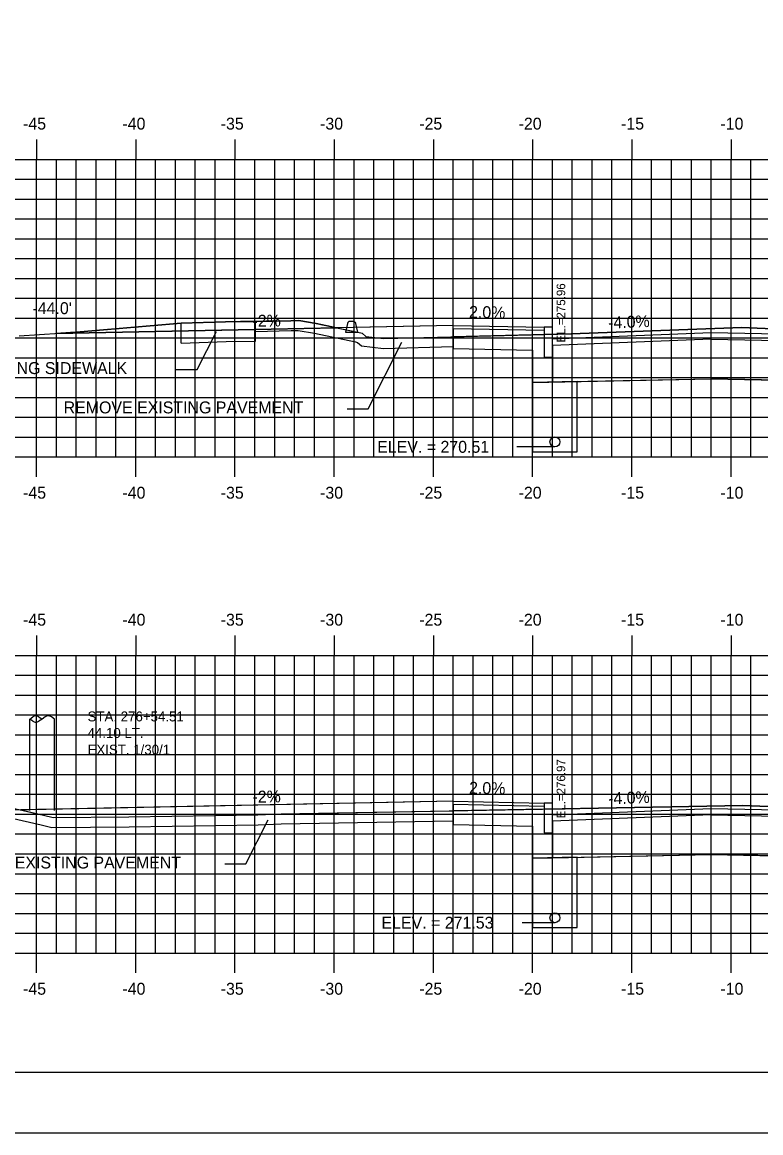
# Model space of a CAD drawing. Extents: x 854008 to 854178, y 366268 to 366378.
# Drawn here: x 854045.4 to 854082.6, y 366268.2 to 366324.1 of the extents above; entities that cross this region are included whole.
import ezdxf

# ---------------------------------------------------------------- set-up
doc = ezdxf.new("R2010")
doc.units = 0
for name, color, linetype in [('ANNOTATION', 7, 'Continuous'), ('BORDER', 7, 'Continuous'), ('D_Curb_Type_1_Lt', 7, 'Continuous'), ('D_Roadway_Edge_TW', 7, 'Continuous'), ('D_Roadway_FinishedGrade', 7, 'Continuous'), ('D_Roadway_Sidewalks_Paved', 7, 'Continuous'), ('D_Roadway_SubGrade', 7, 'Continuous'), ('D_Text_Monospaced', 7, 'Continuous'), ('D_Text_Standard', 7, 'Continuous'), ('H_V ANNOTATION', 7, 'Continuous'), ('JUNK COM EXC', 7, 'Continuous'), ('JUNK FILL', 7, 'Continuous'), ('junk strct exc', 7, 'Continuous'), ('MAJOR', 7, 'Continuous'), ('MINOR', 7, 'Continuous'), ('PDRAIN', 7, 'Continuous'), ('PLOT BOUNDARY', 7, 'Continuous'), ('S_Curb_Type_3', 7, 'Continuous'), ('S_Roadway_Centerline', 7, 'Continuous'), ('S_Utilities_Pole_Power', 7, 'Continuous')]:
    doc.layers.add(name, color=color, linetype=linetype)

msp = doc.modelspace()

# ---------------------------------------------------------------- linework, layer by layer
at = {"layer": 'ANNOTATION'}
for points in [[(854053.138, 366306.653), (854054.197, 366306.653), (854055.165, 366308.56)], [(854061.752, 366304.671), (854062.811, 366304.671), (854064.517, 366308.029)], [(854055.588, 366281.734), (854056.647, 366281.734), (854057.773, 366283.95)]]:
    msp.add_lwpolyline(points, dxfattribs=at)
at = {"layer": 'BORDER'}
msp.add_line((854016.103, 366271.236), (854176.103, 366271.236), dxfattribs=at)
at = {"layer": 'D_Curb_Type_1_Lt'}
for points in [[(854071.686, 366308.775), (854071.686, 366307.275), (854072.103, 366307.275), (854072.103, 366308.775)], [(854071.686, 366284.792), (854071.686, 366283.292), (854072.103, 366283.292), (854072.103, 366284.792)]]:
    msp.add_lwpolyline(points, close=True, dxfattribs=at)
at = {"layer": 'D_Roadway_Edge_TW'}
for points in [[(854072.103, 366308.192), (854080.103, 366308.512), (854102.103, 366308.072), (854110.099, 366307.751)], [(854072.103, 366308.192), (854080.103, 366308.512), (854102.103, 366308.072), (854110.099, 366307.751)], [(854072.103, 366284.209), (854080.103, 366284.529), (854102.103, 366284.089), (854110.099, 366283.769)]]:
    msp.add_lwpolyline(points, dxfattribs=at)
at = {"layer": 'D_Roadway_FinishedGrade'}
for p, q in [((854067.098, 366308.867), (854047.093, 366308.467)), ((854067.098, 366284.884), (854041.806, 366284.378))]:
    msp.add_line(p, q, dxfattribs=at)
at = {"layer": 'D_Roadway_Sidewalks_Paved'}
for points in [[(854067.098, 366308.867), (854071.686, 366308.775), (854071.686, 366308.608), (854067.098, 366308.7)], [(854067.098, 366284.884), (854071.686, 366284.792), (854071.686, 366284.626), (854067.098, 366284.717)]]:
    msp.add_lwpolyline(points, close=True, dxfattribs=at)
at = {"layer": 'D_Roadway_SubGrade'}
for points in [[(854057.135, 366308.568), (854058.929, 366308.605), (854059.29, 366308.616), (854060.106, 366308.477), (854062.18, 366308.035), (854062.278, 366308.011), (854062.48, 366307.837), (854063.588, 366307.708), (854067.098, 366307.796)], [(854067.098, 366308.7), (854067.098, 366307.7), (854071.103, 366307.62), (854071.103, 366305.998), (854072.103, 366306.018)], [(854043.228, 366284.407), (854046.339, 366283.699), (854046.879, 366283.567), (854050.764, 366283.593), (854057.266, 366283.694), (854058.438, 366283.745), (854067.103, 366283.907)], [(854071.686, 366284.626), (854067.098, 366284.717)], [(854067.098, 366284.717), (854067.098, 366283.717), (854071.103, 366283.637), (854071.103, 366282.015), (854072.103, 366282.035)]]:
    msp.add_lwpolyline(points, dxfattribs=at)
for points in [[(854080.103, 366308.178), (854072.103, 366307.858), (854072.103, 366306.018), (854080.103, 366306.178)], [(854080.103, 366306.178), (854080.103, 366308.178), (854091.103, 366307.958), (854102.103, 366307.738), (854102.103, 366305.738), (854091.103, 366305.958)], [(854080.103, 366284.195), (854072.103, 366283.875), (854072.103, 366282.035), (854080.103, 366282.195)], [(854080.103, 366282.195), (854080.103, 366284.195), (854091.103, 366283.975), (854102.103, 366283.755), (854102.103, 366281.755), (854091.103, 366281.975)]]:
    msp.add_lwpolyline(points, close=True, dxfattribs=at)
at = {"layer": 'D_Text_Standard'}
for points in [[(854072.228, 366302.748), (854070.986, 366302.748), (854070.306, 366302.748)], [(854072.228, 366278.765), (854071.252, 366278.765), (854070.572, 366278.765)]]:
    msp.add_lwpolyline(points, dxfattribs=at)
at = {"layer": 'JUNK COM EXC'}
msp.add_lwpolyline([(854047.093, 366308.467), (854057.095, 366308.667), (854061.225, 366308.749), (854060.2, 366308.968), (854059.325, 366309.117), (854058.916, 366309.105), (854056.383, 366309.06), (854055.631, 366309.052), (854054.515, 366309.015), (854053.398, 366308.978), (854050.847, 366308.763), (854048.296, 366308.548)], close=True, dxfattribs=at)
for points in [[(854115.108, 366307.369), (854111.511, 366307.504), (854105.338, 366307.696), (854093.132, 366308.264), (854091.919, 366308.317), (854082.419, 366308.728), (854081.643, 366308.761), (854073.044, 366308.446), (854067.098, 366308.296), (854067.098, 366307.7), (854071.103, 366307.62), (854071.103, 366305.998), (854080.103, 366306.178), (854111.106, 366305.559), (854111.106, 366307.181), (854115.108, 366307.26), (854115.108, 366307.369)], [(854067.098, 366284.408), (854067.098, 366283.717), (854071.103, 366283.637), (854071.103, 366282.015), (854080.103, 366282.195), (854102.103, 366281.755), (854111.106, 366281.576), (854111.139, 366283.231), (854115.108, 366283.277), (854115.108, 366283.389), (854114.969, 366283.394), (854112.044, 366283.502), (854105.033, 366283.764), (854098.156, 366284.024), (854091.667, 366284.28), (854089.919, 366284.352), (854081.695, 366284.68), (854074.422, 366284.545), (854067.098, 366284.408)]]:
    msp.add_lwpolyline(points, dxfattribs=at)
at = {"layer": 'JUNK FILL'}
for points in [[(854067.103, 366308.296), (854067.103, 366308.867), (854067.098, 366308.867), (854061.225, 366308.749), (854062.29, 366308.522), (854062.513, 366308.469), (854062.691, 366308.316), (854063.611, 366308.208), (854067.103, 366308.296)], [(854067.103, 366284.408), (854067.103, 366284.884), (854067.098, 366284.884), (854045.301, 366284.448), (854046.454, 366284.186), (854046.938, 366284.068), (854050.758, 366284.093), (854057.251, 366284.194), (854058.422, 366284.245), (854067.103, 366284.408)]]:
    msp.add_lwpolyline(points, dxfattribs=at)
at = {"layer": 'junk strct exc'}
for points in [[(854071.103, 366305.998), (854071.103, 366302.498), (854073.353, 366302.498), (854073.353, 366306.043)], [(854071.103, 366282.015), (854071.103, 366278.515), (854073.353, 366278.515), (854073.353, 366282.06)]]:
    msp.add_lwpolyline(points, close=True, dxfattribs=at)
at = {"layer": 'MAJOR'}
for p, q in [((854046.103, 366318.238), (854046.103, 366317.236)), ((854051.103, 366318.238), (854051.103, 366317.236)), ((854056.103, 366318.238), (854056.103, 366317.236)), ((854061.103, 366318.238), (854061.103, 366317.236)), ((854066.103, 366318.238), (854066.103, 366317.236)), ((854071.103, 366318.238), (854071.103, 366317.236)), ((854076.103, 366318.238), (854076.103, 366317.236)), ((854081.103, 366318.238), (854081.103, 366317.236)), ((854021.103, 366317.236), (854161.103, 366317.236)), ((854021.103, 366317.236), (854161.103, 366317.236)), ((854046.103, 366302.236), (854046.103, 366317.236)), ((854051.103, 366302.236), (854051.103, 366317.236)), ((854056.103, 366302.236), (854056.103, 366317.236)), ((854061.103, 366302.236), (854061.103, 366317.236)), ((854066.103, 366302.236), (854066.103, 366317.236)), ((854071.103, 366302.236), (854071.103, 366317.236)), ((854076.103, 366302.236), (854076.103, 366317.236)), ((854081.103, 366302.236), (854081.103, 366317.236)), ((854021.103, 366312.236), (854161.103, 366312.236)), ((854021.103, 366307.236), (854161.103, 366307.236)), ((854021.103, 366302.236), (854161.103, 366302.236)), ((854021.103, 366302.236), (854161.103, 366302.236)), ((854046.103, 366301.234), (854046.103, 366302.236)), ((854051.103, 366301.234), (854051.103, 366302.236)), ((854056.103, 366301.234), (854056.103, 366302.236)), ((854061.103, 366301.234), (854061.103, 366302.236)), ((854066.103, 366301.234), (854066.103, 366302.236)), ((854071.103, 366301.234), (854071.103, 366302.236)), ((854076.103, 366301.234), (854076.103, 366302.236)), ((854081.103, 366301.234), (854081.103, 366302.236)), ((854046.103, 366293.238), (854046.103, 366292.236)), ((854051.103, 366293.238), (854051.103, 366292.236)), ((854056.103, 366293.238), (854056.103, 366292.236)), ((854061.103, 366293.238), (854061.103, 366292.236)), ((854066.103, 366293.238), (854066.103, 366292.236)), ((854071.103, 366293.238), (854071.103, 366292.236)), ((854076.103, 366293.238), (854076.103, 366292.236)), ((854081.103, 366293.238), (854081.103, 366292.236)), ((854021.103, 366292.236), (854161.103, 366292.236)), ((854021.103, 366292.236), (854161.103, 366292.236)), ((854046.103, 366277.236), (854046.103, 366292.236)), ((854051.103, 366277.236), (854051.103, 366292.236)), ((854056.103, 366277.236), (854056.103, 366292.236)), ((854061.103, 366277.236), (854061.103, 366292.236)), ((854066.103, 366277.236), (854066.103, 366292.236)), ((854071.103, 366277.236), (854071.103, 366292.236)), ((854076.103, 366277.236), (854076.103, 366292.236)), ((854081.103, 366277.236), (854081.103, 366292.236)), ((854021.103, 366287.236), (854161.103, 366287.236)), ((854021.103, 366282.236), (854161.103, 366282.236)), ((854021.103, 366277.236), (854161.103, 366277.236)), ((854021.103, 366277.236), (854161.103, 366277.236)), ((854046.103, 366276.234), (854046.103, 366277.236)), ((854051.103, 366276.234), (854051.103, 366277.236)), ((854056.103, 366276.234), (854056.103, 366277.236)), ((854061.103, 366276.234), (854061.103, 366277.236)), ((854066.103, 366276.234), (854066.103, 366277.236)), ((854071.103, 366276.234), (854071.103, 366277.236)), ((854076.103, 366276.234), (854076.103, 366277.236)), ((854081.103, 366276.234), (854081.103, 366277.236))]:
    msp.add_line(p, q, dxfattribs=at)
at = {"layer": 'MINOR'}
for p, q in [((854047.103, 366302.236), (854047.103, 366317.236)), ((854048.103, 366302.236), (854048.103, 366317.236)), ((854049.103, 366302.236), (854049.103, 366317.236)), ((854050.103, 366302.236), (854050.103, 366317.236)), ((854052.103, 366302.236), (854052.103, 366317.236)), ((854053.103, 366302.236), (854053.103, 366317.236)), ((854054.103, 366302.236), (854054.103, 366317.236)), ((854055.103, 366302.236), (854055.103, 366317.236)), ((854057.103, 366302.236), (854057.103, 366317.236)), ((854058.103, 366302.236), (854058.103, 366317.236)), ((854059.103, 366302.236), (854059.103, 366317.236)), ((854060.103, 366302.236), (854060.103, 366317.236)), ((854062.103, 366302.236), (854062.103, 366317.236)), ((854063.103, 366302.236), (854063.103, 366317.236)), ((854064.103, 366302.236), (854064.103, 366317.236)), ((854065.103, 366302.236), (854065.103, 366317.236)), ((854067.103, 366302.236), (854067.103, 366317.236)), ((854068.103, 366302.236), (854068.103, 366317.236)), ((854069.103, 366302.236), (854069.103, 366317.236)), ((854070.103, 366302.236), (854070.103, 366317.236)), ((854072.103, 366302.236), (854072.103, 366317.236)), ((854073.103, 366302.236), (854073.103, 366317.236)), ((854074.103, 366302.236), (854074.103, 366317.236)), ((854075.103, 366302.236), (854075.103, 366317.236)), ((854077.103, 366302.236), (854077.103, 366317.236)), ((854078.103, 366302.236), (854078.103, 366317.236)), ((854079.103, 366302.236), (854079.103, 366317.236)), ((854080.103, 366302.236), (854080.103, 366317.236)), ((854082.103, 366302.236), (854082.103, 366317.236)), ((854021.103, 366316.236), (854161.103, 366316.236)), ((854021.103, 366315.236), (854161.103, 366315.236)), ((854021.103, 366314.236), (854161.103, 366314.236)), ((854021.103, 366313.236), (854161.103, 366313.236)), ((854021.103, 366311.236), (854161.103, 366311.236)), ((854021.103, 366310.236), (854161.103, 366310.236)), ((854021.103, 366309.236), (854161.103, 366309.236)), ((854021.103, 366308.236), (854161.103, 366308.236)), ((854021.103, 366306.236), (854161.103, 366306.236)), ((854021.103, 366305.236), (854161.103, 366305.236)), ((854021.103, 366304.236), (854161.103, 366304.236)), ((854021.103, 366303.236), (854161.103, 366303.236)), ((854047.103, 366277.236), (854047.103, 366292.236)), ((854048.103, 366277.236), (854048.103, 366292.236)), ((854049.103, 366277.236), (854049.103, 366292.236)), ((854050.103, 366277.236), (854050.103, 366292.236)), ((854052.103, 366277.236), (854052.103, 366292.236)), ((854053.103, 366277.236), (854053.103, 366292.236)), ((854054.103, 366277.236), (854054.103, 366292.236)), ((854055.103, 366277.236), (854055.103, 366292.236)), ((854057.103, 366277.236), (854057.103, 366292.236)), ((854058.103, 366277.236), (854058.103, 366292.236)), ((854059.103, 366277.236), (854059.103, 366292.236)), ((854060.103, 366277.236), (854060.103, 366292.236)), ((854062.103, 366277.236), (854062.103, 366292.236)), ((854063.103, 366277.236), (854063.103, 366292.236)), ((854064.103, 366277.236), (854064.103, 366292.236)), ((854065.103, 366277.236), (854065.103, 366292.236)), ((854067.103, 366277.236), (854067.103, 366292.236)), ((854068.103, 366277.236), (854068.103, 366292.236)), ((854069.103, 366277.236), (854069.103, 366292.236)), ((854070.103, 366277.236), (854070.103, 366292.236)), ((854072.103, 366277.236), (854072.103, 366292.236)), ((854073.103, 366277.236), (854073.103, 366292.236)), ((854074.103, 366277.236), (854074.103, 366292.236)), ((854075.103, 366277.236), (854075.103, 366292.236)), ((854077.103, 366277.236), (854077.103, 366292.236)), ((854078.103, 366277.236), (854078.103, 366292.236)), ((854079.103, 366277.236), (854079.103, 366292.236)), ((854080.103, 366277.236), (854080.103, 366292.236)), ((854082.103, 366277.236), (854082.103, 366292.236)), ((854021.103, 366291.236), (854161.103, 366291.236)), ((854021.103, 366290.236), (854161.103, 366290.236)), ((854021.103, 366289.236), (854161.103, 366289.236)), ((854021.103, 366288.236), (854161.103, 366288.236)), ((854021.103, 366286.236), (854161.103, 366286.236)), ((854021.103, 366285.236), (854161.103, 366285.236)), ((854021.103, 366284.236), (854161.103, 366284.236)), ((854021.103, 366283.236), (854161.103, 366283.236)), ((854021.103, 366281.236), (854161.103, 366281.236)), ((854021.103, 366280.236), (854161.103, 366280.236)), ((854021.103, 366279.236), (854161.103, 366279.236)), ((854021.103, 366278.236), (854161.103, 366278.236))]:
    msp.add_line(p, q, dxfattribs=at)
at = {"layer": 'PDRAIN'}
for points in [[(854071.103, 366305.998), (854071.103, 366302.498), (854073.353, 366302.498), (854073.353, 366305.998)], [(854071.103, 366282.015), (854071.103, 366278.515), (854073.353, 366278.515), (854073.353, 366282.015)]]:
    msp.add_lwpolyline(points, dxfattribs=at)
for centre in [(854072.228, 366302.998), (854072.228, 366279.015)]:
    msp.add_circle(centre, 0.25, dxfattribs=at)
at = {"layer": 'PLOT BOUNDARY'}
msp.add_lwpolyline([(854008.01, 366268.177), (854178.01, 366268.177), (854178.01, 366378.177), (854008.01, 366378.177)], close=True, dxfattribs=at)
at = {"layer": 'S_Curb_Type_3'}
for points in [[(854061.768, 366308.967), (854061.665, 366308.522), (854062.29, 366308.522), (854062.188, 366308.967)], [(854062.066, 366309.064), (854061.89, 366309.064)]]:
    msp.add_lwpolyline(points, dxfattribs=at)
for centre, start, end in [((854061.89, 366308.939), 90, 167.0054), ((854062.066, 366308.939), 12.9946, 90)]:
    msp.add_arc(centre, 0.125, start, end, dxfattribs=at)
at = {"layer": 'S_Roadway_Centerline'}
for p, q in [((854053.398, 366307.977), (854053.398, 366308.978)), ((854057.135, 366308.068), (854057.135, 366309.068))]:
    msp.add_line(p, q, dxfattribs=at)
for points in [[(854045.227, 366308.341), (854048.296, 366308.548), (854053.398, 366308.978), (854055.631, 366309.052), (854057.135, 366309.068), (854058.916, 366309.105), (854059.325, 366309.117), (854060.2, 366308.968), (854062.29, 366308.522), (854062.513, 366308.469), (854062.691, 366308.316), (854063.611, 366308.208), (854073.044, 366308.446), (854081.643, 366308.761), (854082.419, 366308.728), (854091.919, 366308.317), (854093.132, 366308.264), (854105.338, 366307.696), (854111.511, 366307.504), (854116.772, 366307.307), (854117.147, 366307.541), (854117.398, 366307.685), (854122.963, 366307.541)], [(854053.398, 366307.977), (854055.653, 366308.052), (854057.135, 366308.068)], [(854042.191, 366285.155), (854046.454, 366284.186), (854046.938, 366284.068), (854050.758, 366284.093), (854057.251, 366284.194), (854058.422, 366284.245), (854074.422, 366284.545), (854081.695, 366284.68), (854089.919, 366284.352), (854091.667, 366284.28), (854098.156, 366284.024), (854105.033, 366283.764), (854112.044, 366283.502), (854114.969, 366283.394), (854115.555, 366283.373), (854116.422, 366283.344), (854117.122, 366283.782), (854117.147, 366283.798), (854117.542, 366283.751), (854119.24, 366283.569), (854127.488, 366282.734)]]:
    msp.add_lwpolyline(points, dxfattribs=at)
at = {"layer": 'S_Utilities_Pole_Power'}
for p, q in [((854045.756, 366289.031), (854045.912, 366289.141)), ((854045.756, 366284.412), (854045.759, 366289.031)), ((854045.912, 366288.92), (854045.756, 366289.031)), ((854046.224, 366289.141), (854046.381, 366289.031)), ((854046.381, 366289.031), (854046.224, 366288.92)), ((854046.537, 366289.141), (854046.381, 366289.031)), ((854047.006, 366289.031), (854046.85, 366289.141)), ((854047.006, 366284.412), (854047.009, 366289.031))]:
    msp.add_line(p, q, dxfattribs=at)
for centre, start, end in [((854046.068, 366288.92), 90, 125.2644), ((854046.068, 366289.141), 234.7356, 270), ((854046.068, 366288.92), 54.7356, 90), ((854046.068, 366289.141), 270, 305.2644), ((854046.693, 366288.92), 90, 125.2644), ((854046.693, 366288.92), 54.7356, 90)]:
    msp.add_arc(centre, 0.271, start, end, dxfattribs=at)

# ---------------------------------------------------------------- texts
at = {"layer": 'ANNOTATION'}
for s, rotation, p in [('2.0%', 358.8542, (854067.896, 366309.251)), ('-2%', 0.7274, (854056.989, 366308.796)), ('-4.0%', 2.2906, (854074.919, 366308.705)), ('2.0%', 358.8542, (854067.896, 366285.268)), ('-2%', 0.7274, (854056.989, 366284.813)), ('-4.0%', 2.2906, (854074.919, 366284.722))]:
    msp.add_text(s, height=0.6, rotation=rotation, dxfattribs=at).set_placement(p)
for s, p in [('REMOVE EXISTING SIDEWALK', (854038.853, 366306.416)), ('REMOVE EXISTING PAVEMENT', (854047.467, 366304.434)), ('REMOVE EXISTING PAVEMENT', (854041.303, 366281.497))]:
    msp.add_text(s, height=0.6, dxfattribs=at).set_placement(p)
at = {"layer": 'D_Text_Monospaced'}
for s, height, p in [('STA. 276+54.51', 0.49998, (854048.672, 366288.91)), ('44.10 LT.', 0.5, (854048.672, 366288.076)), ('EXIST. 1/30/1', 0.49998, (854048.672, 366287.236))]:
    msp.add_text(s, height=height, dxfattribs=at).set_placement(p)
at = {"layer": 'D_Text_Standard'}
for s, p in [(' EL.=275.96', (854072.747, 366307.846)), (' EL.=276.97', (854072.747, 366283.863))]:
    msp.add_text(s, height=0.4335, rotation=90, dxfattribs=at).set_placement(p)
for s, p in [("-44.0'", (854045.897, 366309.436)), ('ELEV. = 270.51', (854063.27, 366302.448)), ('ELEV. = 271.53', (854063.487, 366278.465))]:
    msp.add_text(s, height=0.6, dxfattribs=at).set_placement(p)
at = {"layer": 'H_V ANNOTATION'}
for s, p in [('-45', (854045.421, 366318.736)), ('-40', (854050.429, 366318.736)), ('-35', (854055.383, 366318.736)), ('-30', (854060.391, 366318.736)), ('-25', (854065.389, 366318.736)), ('-20', (854070.397, 366318.736)), ('-15', (854075.56, 366318.736)), ('-10', (854080.568, 366318.736)), ('-45', (854045.421, 366300.136)), ('-40', (854050.429, 366300.136)), ('-35', (854055.383, 366300.136)), ('-30', (854060.391, 366300.136)), ('-25', (854065.389, 366300.136)), ('-20', (854070.397, 366300.136)), ('-15', (854075.56, 366300.136)), ('-10', (854080.568, 366300.136)), ('-45', (854045.421, 366293.736)), ('-40', (854050.429, 366293.736)), ('-35', (854055.383, 366293.736)), ('-30', (854060.391, 366293.736)), ('-25', (854065.389, 366293.736)), ('-20', (854070.397, 366293.736)), ('-15', (854075.56, 366293.736)), ('-10', (854080.568, 366293.736)), ('-45', (854045.421, 366275.136)), ('-40', (854050.429, 366275.136)), ('-35', (854055.383, 366275.136)), ('-30', (854060.391, 366275.136)), ('-25', (854065.389, 366275.136)), ('-20', (854070.397, 366275.136)), ('-15', (854075.56, 366275.136)), ('-10', (854080.568, 366275.136))]:
    msp.add_text(s, height=0.6, dxfattribs=at).set_placement(p)

doc.saveas('drawing.dxf')
